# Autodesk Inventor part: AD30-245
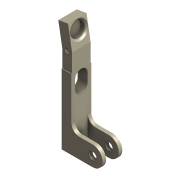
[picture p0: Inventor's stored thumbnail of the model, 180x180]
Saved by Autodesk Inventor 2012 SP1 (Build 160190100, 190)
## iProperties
Shininess: 0.0
Created: 2000-07
Part Number: AD30-245
User Status: RELEASED
Description: DETENT PIVOT
Document SubType Name: Modeling
Designer: Ron
Mass: 5.60821 g
Surface Area: 41.9381 cm^2
Volume: 5.60821 cm^3
Density: 1 g/cm^3
Material: Default
Density: 0.0
Volumn: 0.0
Area: 0.0
PropertySet Name: Model Information
Control State: 0
Master: False
Checked Out: False
Author: Ron
Revision Number: A
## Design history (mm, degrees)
node "Extrusion1" dims "d11" = 12.7, "d12" = 0
  sketch "Sketch1"
    geometry: L1 (16.777, -43.65)-(3.127, -43.65); L2 (3.127, -43.65)-(3.127, 0.551); L3 (3.127, 0.551)-(0.522, 15.323); L4 (0.522, 15.323)-(-5.731, 14.221); L5 (-5.731, 14.221)-(-3.223, -0.004); L6 (-3.223, -0.004)-(-3.223, -56.35); L7 (-3.223, -56.35)-(16.777, -56.35); L8 (0, 0)-(-2.605, 14.772); L9 (0, 0)-(0, -56.35); L10 (0, 0)-(3.127, 0.551); L11 (3.127, -43.65)-(-3.223, -43.65); C1 r 2.381 at (16.777, -50); C2 r 1.6 at (0, 0); A1 r 6.35 centre (16.777, -50) between (16.777, -43.65) and (16.777, -56.35)
    constraints: 22 end point, 6 perpendicular, 3 centre point, 3 parallel, 2 coincident, 2 point on circle, 2 point on line, 2 tangent, 1 equal length, 1 horizontal, 1 midpoint
    dimensions: "d0" = 3.2 diameter of C2; "d2" = 20 distance from line of C1.centre L6; "d3" = 12.7 diameter of A1; "d4" = 50 vertical distance of C1.centre C2.centre; "d6" = 10 deg angle of L3 L2; "d8" = 15 distance from line of L4 C2.centre; "d31" = 4.7625 diameter of C1; "d33" = 6.35 distance of L3.end L4.end
node "Extrusion2" dims "d14" = 12.7, "d15" = 0
  sketch "Sketch2"
    geometry: L1 (20, 12.7)-(0, 12.7) reference; L2 (0, 0)-(20, 0) reference; L3 (6.35, 0)-(6.35, 12.7) reference; L4 (6.35, 10.45)-(26.35, 10.45); L5 (26.35, 10.45)-(26.35, 2.25); L6 (26.35, 2.25)-(6.35, 2.25); L7 (6.35, 2.25)-(6.35, 10.45); L8 (26.35, 0)-(26.35, 12.7) reference; L9 (8.872, 10.45)-(8.872, 12.7); L10 (8.872, 2.25)-(8.872, 0)
    constraints: 12 end point, 5 point on line, 3 collinear, 3 parallel, 1 horizontal, 1 perpendicular
    dimensions: "d34" = 2.25 distance between parallel lines of L2 L6
node "Extrusion3" dims "d18" = 12.7, "d19" = 0
  sketch "Sketch3"
    geometry: L1 (0, 0)-(0, 44.201) reference; L2 (-12.7, 44.201)-(-12.7, 0) reference; L3 (-12.3, 32.3)-(-12.7, 32.3); L4 (-12.7, 32.3)-(-12.7, 58.973); L5 (-12.7, 58.973)-(-12.3, 58.973); L6 (-12.3, 58.973)-(-12.3, 32.3); L7 (0, 32.3)-(-0.4, 32.3); L8 (-0.4, 32.3)-(-0.4, 58.973); L9 (-0.4, 58.973)-(0, 58.973); L10 (0, 58.973)-(0, 32.3); L11 (0, 58.973)-(-12.7, 58.973) reference; L12 (0, -12.7)-(-12.7, -12.7) reference
    constraints: 16 end point, 5 collinear, 4 parallel, 2 horizontal, 2 perpendicular, 1 point on line
    dimensions: "d16" = 11.9 distance between parallel lines of L8 L6; "d17" = 45 distance from line of L12 L3.start
node "Extrusion4" dims "d22" = 4, "d23" = 0
  sketch "Sketch4"
    geometry: L1 (11.9, 0)-(0, 0) reference; L2 (11.9, -15)-(0, -15) reference; L3 (5.95, 0)-(5.95, -6); C1 r 4.763 at (5.95, -6)
    constraints: 2 end point, 1 centre point, 1 coincident, 1 midpoint, 1 perpendicular
    dimensions: "d20" = 9.525 diameter of C1; "d21" = 6 distance from line of L1 C1.centre
node "Chamfer1" dims "d24" = 1, "d25" = 1, "d32" = 45 deg
node "Extrusion5" dims "d29" = 2, "d30" = 0
  sketch "Sketch5" dims "d28" = 8
    geometry: L1 (0, 0)-(12.7, 0) reference; L2 (0.4, 56.346)-(12.3, 56.346) reference; L3 (10.35, 41)-(2.35, 41); L4 (2.35, 41)-(2.35, 35); L5 (2.35, 35)-(10.35, 35); L6 (10.35, 35)-(10.35, 41); L7 (6.35, 56.346)-(6.35, 41); 1 further point
    constraints: 10 end point, 3 midpoint, 3 parallel, 2 horizontal alignment, 1 horizontal, 1 perpendicular, 4 other
    dimensions: "d26" = 6 distance of point (6.35, 35) L7.end; "d27" = 35 distance from line of point (6.35, 35) L1
fillet "Fillet1" dims "d35" = 5
body "Solid1"
